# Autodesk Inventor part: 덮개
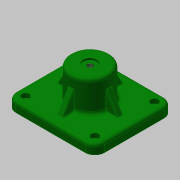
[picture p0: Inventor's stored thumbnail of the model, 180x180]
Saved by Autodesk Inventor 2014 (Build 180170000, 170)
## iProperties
Created: 2017-08
Part Number: 덮개
Material: 알루미늄 6061
Document SubType Name: Modeling
Designer: mduedu
Density: 1 g/cm^3
Appearance: 진녹색
Author: mduedu
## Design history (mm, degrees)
sketch "스케치1"
  geometry: L1 (46, -41)-(-46, -41); L2 (-46, -41)-(-46, 41); L3 (-46, 41)-(46, 41); L4 (46, 41)-(46, -41); 1 further point
  constraints: 8 end point, 2 parallel, 1 horizontal, 1 perpendicular
  dimensions: "d0" = 92 distance of L2.end L3.end; "d2" = 82 distance of L1.end L2.end; "d3" = 41 distance from line of L3 point (0, 0) (= 0.5 x d2); "d4" = 46 distance from line of point (0, 0) L4 (= 0.5 x d0)
extrude "돌출1" new body sketch "스케치1" distance "d5" = 10; taper "d6" = 0 deg
sketch "스케치2"
  geometry: C1 r 20 at (0, 0); 1 further point
  constraints: 1 centre point, 1 coincident
  dimensions: "d55" = 40 diameter of C1
extrude "돌출2" join sketch "스케치2" distance "d9" = 32; taper "d10" = 0 deg
sketch "스케치3"
  geometry: L1 (-26, -26)-(26, -26); L2 (26, -26)-(26, 26); L3 (26, 26)-(-26, 26); L4 (-26, 26)-(-26, -26); L5 (-26, -26)-(26, 26); L6 (26, -26)-(-26, 26); 1 further point
  constraints: 12 end point, 2 midpoint, 2 parallel, 2 perpendicular, 1 horizontal
  dimensions: "d11" = 52 distance of L3.end L2.end
extrude "돌출3" join sketch "스케치3" distance "d12" = 6; taper "d13" = 0 deg
sketch "스케치4"
  geometry: L1 (-17, -17)-(17, -17); L2 (17, -17)-(17, 17); L3 (17, 17)-(-17, 17); L4 (-17, 17)-(-17, -17); L5 (-17, -17)-(17, 17); L6 (17, -17)-(-17, 17); 1 further point
  constraints: 12 end point, 2 midpoint, 2 parallel, 2 perpendicular, 1 horizontal
  dimensions: "d14" = 34 distance of L2.end L3.end
extrude "돌출4" cut sketch "스케치4" distance "d16" = 5; taper "d17" = 0 deg
sketch "스케치5"
  geometry: C1 r 9 at (0, 0); 1 further point
  constraints: 1 centre point, 1 coincident
  dimensions: "d18" = 18 diameter of C1
extrude "돌출5" cut sketch "스케치5" distance "d19" = 34; taper "d20" = 0 deg
sketch "스케치6"
  geometry: 2 further points
  constraints: 1 coincident
hole "구멍1" sketch "스케치6" at (0, 0) diameter "d21" = 5.917; stored, may be unused: countersink angle "d25" = 90 deg, drill point angle "d27" = 118 deg; dims "d22" = 6, "d23" = 14, "d24" = 2, "d26" = 8
fillet "모깎기1" dims "d36" = 10
fillet "모깎기3" dims "d38" = 3
fillet "모깎기4" dims "d39" = 3
fillet "모깎기5" dims "d40" = 3
chamfer "모따기1" distance "d41" = 1; stored, may be unused: second distance "d42" = 2, angle "d43" = 45 deg
fillet "모깎기6" dims "d44" = 3
fillet "모깎기7" dims "d45" = 3
fillet "모깎기8" dims "d46" = 3
sketch "스케치8"
  geometry: A1 r 10 centre (-36, -31) between (-46, -31) and (-36, -41) reference; A2 r 10 centre (-36, 31) between (-36, 41) and (-46, 31) reference; A3 r 10 centre (36, 31) between (46, 31) and (36, 41) reference; A4 r 10 centre (36, -31) between (36, -41) and (46, -31) reference; 5 further points
  constraints: 4 coincident
sketch "스케치9"
  geometry: 4 further points
  constraints: 4 other
hole "구멍3" sketch "스케치9" at (-36, -31), (-36, 31), (36, 31), (36, -31) diameter "d48" = 4.5; stored, may be unused: countersink angle "d52" = 90 deg, drill point angle "d54" = 0 deg; dims "d49" = 6, "d50" = 8, "d51" = 4.6, "d53" = 8
sketch "스케치10"
  geometry: L1 (-7, 40)-(-2.958, 40) reference; L2 (-2.958, 40)-(-2.958, 33) reference; L3 (-2.958, 33)-(-6, 33) reference; L4 (-9, 30)-(-9, -1) reference; L5 (-9, -1)-(-14, -1) reference; L6 (-17, -4)-(-17, -6) reference; L7 (-17, -6)-(-25, -6) reference; L8 (-25, -6)-(-26, -5) reference; L9 (-26, -5)-(-26, 0) reference; L10 (-26, 0)-(-46, 0) reference; L11 (-46, 0)-(-46, 7) reference; L12 (-43, 10)-(-23, 10) reference; L13 (-20, 13)-(-20, 39) reference; L14 (-17, 42)-(-7, 42) reference; L15 (-7, 42)-(-7, 40) reference; L16 (2.958, 40)-(7, 40) reference; L17 (7, 40)-(7, 42) reference; L18 (7, 42)-(17, 42) reference; L19 (20, 39)-(20, 13) reference; L20 (23, 10)-(43, 10) reference; L21 (46, 7)-(46, 0) reference; L22 (46, 0)-(26, 0) reference; L23 (26, 0)-(26, -5) reference; L24 (26, -5)-(25, -6) reference; L25 (25, -6)-(17, -6) reference; L26 (17, -6)-(17, -4) reference; L27 (14, -1)-(9, -1) reference; L28 (9, -1)-(9, 30) reference; L29 (6, 33)-(2.958, 33) reference; L30 (2.958, 33)-(2.958, 40) reference; L31 (31.547, 10)-(20, 30); A1 r 3 centre (-6, 30) between (-6, 33) and (-9, 30) reference; A2 r 3 centre (-14, -4) between (-14, -1) and (-17, -4) reference; A3 r 3 centre (-43, 7) between (-43, 10) and (-46, 7) reference; A4 r 3 centre (-23, 13) between (-23, 10) and (-20, 13) reference; A5 r 3 centre (-17, 39) between (-17, 42) and (-20, 39) reference; A6 r 3 centre (17, 39) between (20, 39) and (17, 42) reference; A7 r 3 centre (23, 13) between (20, 13) and (23, 10) reference; A8 r 3 centre (43, 7) between (46, 7) and (43, 10) reference; A9 r 3 centre (14, -4) between (17, -4) and (14, -1) reference; A10 r 3 centre (6, 30) between (9, 30) and (6, 33) reference; 1 further point
  constraints: 2 end point, 2 point on line
  dimensions: "d56" = 20 distance from line of L31.end L20; "d57" = 120 deg angle of L31 L20
feature "리브1" sketch "스케치10" dims "d58" = 1, "d59" = 6, "d60" = 0, "d61" = 0, "d62" = 1, "d63" = 1
fillet "모깎기9" dims "d64" = 1
fillet "모깎기10" dims "d65" = 1
node "솔리드1"
pattern_circular "원형 패턴1" dims "d67" = 360 deg
node "절단 모서리 투영1"
